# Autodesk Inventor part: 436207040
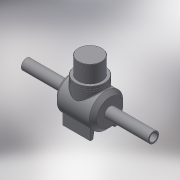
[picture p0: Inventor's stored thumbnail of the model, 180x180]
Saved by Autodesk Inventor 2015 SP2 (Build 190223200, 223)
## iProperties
Created: 2017-08
Part Number: 436207040
Material: Generic
Description: PLASSON PE BALL VALVE 40
Document SubType Name: Modeling
Designer: Кирилл
Density: 1 g/cm^3
Appearance: Default
Author: Кирилл
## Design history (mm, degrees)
derived "436207.ipt"
feature "Solid1::436207.ipt"
feature "Solid2::436207.ipt"
tag "TaggingFeature1"
body "Solid1"
other parameters: "d3" = 103, "d6" = 9, "d8" = 94, "d11" = 56, "d12" = 0.7, "d13" = 4, "d14" = 4, "d16" = 100 deg, "d17" = 32, "d18" = 6.4, "d20" = 65, "d21" = 0, "d22" = 0.7, "d26" = 4, "d28" = 0, "d29" = 1.4, "s_" = 4, "L_1" = 103, "B_" = 65, "H_" = 94
